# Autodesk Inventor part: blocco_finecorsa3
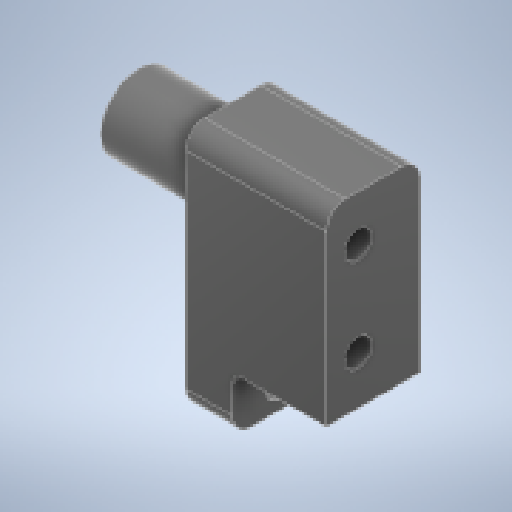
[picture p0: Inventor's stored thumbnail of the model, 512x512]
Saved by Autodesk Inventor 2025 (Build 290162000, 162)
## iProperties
Created: 2026-03
Part Number: blocco_finecorsa3
Material: Generico
Document SubType Name: Modeling
Designer: Ryzen5700u
Density: 1 g/cm^3
Appearance: Liscia - Nero
Author: Ryzen5700u
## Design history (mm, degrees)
sketch "Schizzo1"
  geometry: L1 (10, 5)-(-10, 5); L2 (-10, 5)-(-10, -5); L3 (-10, -5)-(10, -5); L4 (10, -5)-(10, 5); L5 (10, 5)-(-10, -5); L6 (-10, 5)-(10, -5); 1 further point
  constraints: 12 end point, 2 midpoint, 2 parallel, 1 horizontal, 1 perpendicular
  dimensions: "d0" = 20 distance of L3.end L2.end; "d1" = 10 distance of L2.end L1.end
extrude "Estrusione1" new body sketch "Schizzo1" distance "d2" = 15; taper "d3" = 0 deg
sketch "Schizzo2"
  geometry: C1 r 4 at (0, 4); 1 further point
  constraints: 1 centre point
  dimensions: "d4" = 8 diameter of C1; "d5" = 4 distance of point (0, 0) C1.centre
extrude "Estrusione2" join sketch "Schizzo2" distance "d6" = 10; taper "d7" = 0 deg
sketch "Schizzo3"
  geometry: C1 r 1.25 at (-1.6, 5.125) reference; C2 r 1.25 at (-1.6, -4.875) reference; 1 further point
hole "Foro1" sketch "Schizzo3" at (-1.6, 5.125), (-1.6, -4.875) diameter "d9" = 2.9; stored, may be unused: countersink angle "d13" = 90 deg, drill point angle "d15" = 118 deg; dims "d10" = 6, "d11" = 5.5, "d12" = 2.9, "d14" = 8
sketch "Schizzo4"
  geometry: L1 (5, -10)-(-5, -10) reference; L2 (5, 10)-(5, -10) reference; L3 (-5, 10)-(5, 10) reference; L4 (-5, -10)-(-5, 10) reference; L5 (5, -10)-(-5, -10) reference; L6 (5, -10)-(-5, -10); L7 (-5, -10)-(-5, -16); L8 (-5, -16)-(5, -16); L9 (5, -16)-(5, -10); C1 r 4 at (0, 4) reference; 2 further points
  constraints: 8 end point, 2 parallel, 1 horizontal, 1 perpendicular
  dimensions: "d16" = 6 distance of L7.end L6.end
extrude "Estrusione3" join sketch "Schizzo4" distance "d17" = 5; taper "d18" = 0 deg
fillet "Raccordo2" dims "d19" = 1
sketch "Schizzo5"
  geometry: L1 (-5, -16)-(5, -16) reference; 2 further points
  dimensions: "d27" = 2.5 distance from line of L1 point (0, -13.5)
hole "Foro2" sketch "Schizzo5" at (0, -13.5) diameter "d20" = 2.9; stored, may be unused: countersink angle "d24" = 90 deg, drill point angle "d26" = 118 deg; dims "d21" = 6, "d22" = 4, "d23" = 2, "d25" = 8
fillet "Raccordo3" dims "d28" = 2
node "Solido1"
node "Riferimento1"
node "Riferimento2"
node "Linea chiusa proiettata1"
